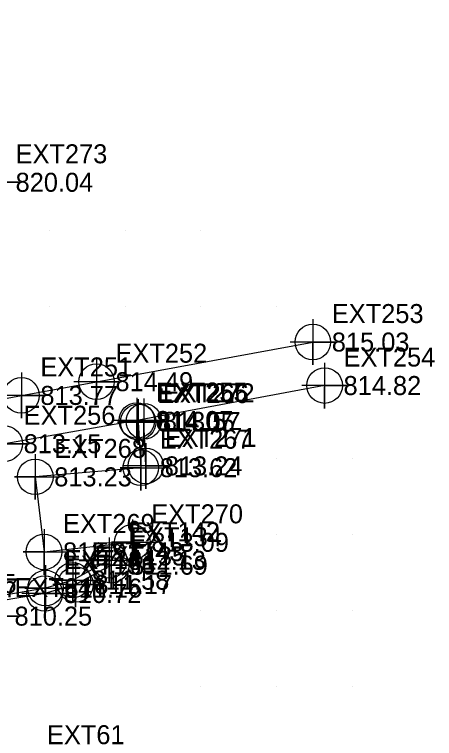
# Model space of a CAD drawing. Extents: x 1762120 to 1766775, y 709485 to 712965.
# Drawn here: x 1763875.4 to 1763930.8, y 712653.2 to 712748.4 of the extents above; entities that cross this region are included whole.
import ezdxf

# ---------------------------------------------------------------- set-up
doc = ezdxf.new("R2010")
doc.units = 0
for name, color, linetype in [('Exist Building Cogo Elevation', 7, 'Continuous'), ('Exist Building Cogo Number', 7, 'Continuous'), ('Exist Building Cogo Point CELL', 7, 'Continuous'), ('Exist DTM Drainline', 7, 'Continuous'), ('Exist DTM Drainline Cogo Elevation', 7, 'Continuous'), ('Exist DTM Drainline Cogo Number', 7, 'Continuous'), ('Exist DTM Drainline Cogo Point CELL', 7, 'Continuous'), ('Exist DTM QL2 LIDAR Elevation Point', 7, 'Continuous'), ('Exist Roads Curbs', 7, 'Continuous'), ('Exist Roads Curbs Cogo Elevation', 7, 'Continuous'), ('Exist Roads Curbs Cogo Number', 7, 'Continuous'), ('Exist Roads Curbs Cogo Point CELL', 7, 'Continuous'), ('Exist Roads EOP Cogo Elevation', 7, 'Continuous'), ('Exist Roads EOP Cogo Number', 7, 'Continuous'), ('Exist Roads EOP Cogo Point CELL', 7, 'Continuous'), ('Exist Roads EOP Other', 7, 'Continuous'), ('Exist Roads EOP Other Cogo Elevation', 7, 'Continuous'), ('Exist Roads EOP Other Cogo Number', 7, 'Continuous'), ('Exist Roads EOP Other Cogo Point CELL', 7, 'Continuous')]:
    doc.layers.add(name, color=color, linetype=linetype)

msp = doc.modelspace()

# ---------------------------------------------------------------- linework, layer by layer
at = {"layer": 'Exist Building Cogo Point CELL'}
msp.add_lwpolyline([(1763873.081, 712729.353), (1763873.081, 712723.353), (1763873.081, 712726.353), (1763876.081, 712726.353), (1763870.081, 712726.353)], dxfattribs=at)
at = {"layer": 'Exist DTM Drainline'}
msp.add_line((1763892.736, 712689.033), (1763892.48, 712694.893), dxfattribs=at)
msp.add_lwpolyline([(1763888.176, 712675.965), (1763883.465, 712673.426), (1763879.421, 712672.239), (1763861.295, 712669.219), (1763855.834, 712669.139), (1763849.992, 712671.404), (1763845.815, 712675.27), (1763843.641, 712680.197), (1763837.254, 712719.085), (1763830.877, 712756.626), (1763824.422, 712795.511), (1763818.53, 712833.611)], dxfattribs=at)
at = {"layer": 'Exist DTM Drainline Cogo Point CELL'}
for points in [[(1763892.48, 712697.893), (1763892.48, 712691.893), (1763892.48, 712694.893), (1763895.48, 712694.893), (1763889.48, 712694.893)], [(1763892.736, 712692.033), (1763892.736, 712686.033), (1763892.736, 712689.033), (1763895.736, 712689.033), (1763889.736, 712689.033)], [(1763888.176, 712678.965), (1763888.176, 712672.965), (1763888.176, 712675.965), (1763891.176, 712675.965), (1763885.176, 712675.965)], [(1763883.465, 712676.426), (1763883.465, 712670.426), (1763883.465, 712673.426), (1763886.465, 712673.426), (1763880.465, 712673.426)], [(1763879.421, 712675.239), (1763879.421, 712669.239), (1763879.421, 712672.239), (1763882.421, 712672.239), (1763876.421, 712672.239)]]:
    msp.add_lwpolyline(points, dxfattribs=at)
for centre in [(1763892.48, 712694.893), (1763892.736, 712689.033), (1763888.176, 712675.965), (1763883.465, 712673.426), (1763879.421, 712672.239)]:
    msp.add_circle(centre, 2.344, dxfattribs=at)
at = {"layer": 'Exist DTM QL2 LIDAR Elevation Point'}
for p, q in [((1763880, 712720), (1763880, 712720)), ((1763890, 712720), (1763890, 712720)), ((1763900, 712720), (1763900, 712720)), ((1763880, 712710), (1763880, 712710)), ((1763890, 712710), (1763890, 712710)), ((1763900, 712710), (1763900, 712710)), ((1763910, 712710), (1763910, 712710)), ((1763920, 712700), (1763920, 712700)), ((1763900, 712690), (1763900, 712690)), ((1763910, 712690), (1763910, 712690)), ((1763920, 712690), (1763920, 712690)), ((1763900, 712680), (1763900, 712680)), ((1763910, 712680), (1763910, 712680)), ((1763920, 712680), (1763920, 712680)), ((1763900, 712670), (1763900, 712670)), ((1763910, 712670), (1763910, 712670)), ((1763920, 712670), (1763920, 712670)), ((1763900, 712660), (1763900, 712660)), ((1763910, 712660), (1763910, 712660)), ((1763920, 712660), (1763920, 712660))]:
    msp.add_line(p, q, dxfattribs=at)
at = {"layer": 'Exist Roads Curbs'}
for points in [[(1763887.913, 712676.609), (1763883.105, 712673.993), (1763879.529, 712672.953), (1763861.13, 712669.797), (1763855.716, 712669.958), (1763851.546, 712671.351), (1763848.135, 712673.751), (1763845.524, 712677.19), (1763844.339, 712680.601), (1763837.881, 712719.135), (1763831.693, 712756.599), (1763825.169, 712795.603), (1763818.676, 712837.176), (1763818.589, 712840.745), (1763820.694, 712846.562), (1763822.71, 712849.767), (1763826.551, 712853.145), (1763830.571, 712855.107), (1763844.339, 712857.64), (1763850.134, 712857.271), (1763855.594, 712854.564), (1763859.316, 712849.842), (1763861.632, 712843.383)], [(1763891.733, 712694.8), (1763892.071, 712688.797), (1763878.17, 712687.59), (1763879.326, 712677.712), (1763890.96, 712678.974)]]:
    msp.add_lwpolyline(points, dxfattribs=at)
at = {"layer": 'Exist Roads Curbs Cogo Point CELL'}
for points in [[(1763891.733, 712697.8), (1763891.733, 712691.8), (1763891.733, 712694.8), (1763889.003, 712694.8), (1763894.733, 712694.8)], [(1763892.071, 712691.797), (1763892.071, 712685.797), (1763892.071, 712688.797), (1763889.341, 712688.797), (1763895.071, 712688.797)], [(1763878.17, 712690.59), (1763878.17, 712684.59), (1763878.17, 712687.59), (1763875.44, 712687.59), (1763881.17, 712687.59)], [(1763890.96, 712681.974), (1763890.96, 712675.974), (1763890.96, 712678.974), (1763888.23, 712678.974), (1763893.96, 712678.974)], [(1763879.326, 712680.712), (1763879.326, 712674.712), (1763879.326, 712677.712), (1763876.596, 712677.712), (1763882.326, 712677.712)], [(1763887.913, 712679.609), (1763887.913, 712673.609), (1763887.913, 712676.609), (1763885.183, 712676.609), (1763890.913, 712676.609)], [(1763883.105, 712676.993), (1763883.105, 712670.993), (1763883.105, 712673.993), (1763880.375, 712673.993), (1763886.105, 712673.993)], [(1763879.529, 712675.953), (1763879.529, 712669.953), (1763879.529, 712672.953), (1763876.799, 712672.953), (1763882.529, 712672.953)]]:
    msp.add_lwpolyline(points, dxfattribs=at)
for centre in [(1763891.733, 712694.8), (1763892.071, 712688.797), (1763878.17, 712687.59), (1763890.96, 712678.974), (1763879.326, 712677.712), (1763887.913, 712676.609), (1763883.105, 712673.993), (1763879.529, 712672.953)]:
    msp.add_circle(centre, 2.344, dxfattribs=at)
at = {"layer": 'Exist Roads EOP Cogo Point CELL'}
msp.add_lwpolyline([(1763872.939, 712672.264), (1763872.939, 712666.264), (1763872.939, 712669.264), (1763875.939, 712669.264), (1763869.939, 712669.264)], dxfattribs=at)
at = {"layer": 'Exist Roads EOP Other'}
for points in [[(1763851.484, 712693.757), (1763858.758, 712695.065), (1763876.347, 712698.307), (1763886.241, 712700.113), (1763914.739, 712705.328)], [(1763916.286, 712699.606), (1763891.551, 712695.001), (1763874.144, 712691.949), (1763852.567, 712687.92)]]:
    msp.add_lwpolyline(points, dxfattribs=at)
at = {"layer": 'Exist Roads EOP Other Cogo Point CELL'}
for points in [[(1763914.739, 712708.328), (1763914.739, 712702.328), (1763914.739, 712705.328), (1763917.739, 712705.328), (1763911.739, 712705.328)], [(1763886.241, 712703.113), (1763886.241, 712697.113), (1763886.241, 712700.113), (1763889.241, 712700.113), (1763883.241, 712700.113)], [(1763916.286, 712702.606), (1763916.286, 712696.606), (1763916.286, 712699.606), (1763919.286, 712699.606), (1763913.286, 712699.606)], [(1763876.347, 712701.307), (1763876.347, 712695.307), (1763876.347, 712698.307), (1763879.347, 712698.307), (1763873.347, 712698.307)], [(1763891.551, 712698.001), (1763891.551, 712692.001), (1763891.551, 712695.001), (1763894.551, 712695.001), (1763888.551, 712695.001)], [(1763874.144, 712694.949), (1763874.144, 712688.949), (1763874.144, 712691.949), (1763877.144, 712691.949), (1763871.144, 712691.949)]]:
    msp.add_lwpolyline(points, dxfattribs=at)
for centre in [(1763914.739, 712705.328), (1763886.241, 712700.113), (1763916.286, 712699.606), (1763876.347, 712698.307), (1763891.551, 712695.001), (1763874.144, 712691.949)]:
    msp.add_circle(centre, 2.344, dxfattribs=at)

# ---------------------------------------------------------------- texts
at = {"layer": 'Exist Building Cogo Elevation'}
msp.add_text('820.04', height=2.5, dxfattribs=at).set_placement((1763875.581, 712725.103))
at = {"layer": 'Exist Building Cogo Number'}
msp.add_text('EXT273', height=2.5, dxfattribs=at).set_placement((1763875.581, 712728.853))
at = {"layer": 'Exist DTM Drainline Cogo Elevation'}
for s, p in [('813.57', (1763894.98, 712693.643)), ('813.24', (1763895.236, 712687.783)), ('811.69', (1763890.676, 712674.715)), ('811.17', (1763885.965, 712672.176)), ('810.72', (1763881.921, 712670.989))]:
    msp.add_text(s, height=2.5, dxfattribs=at).set_placement(p)
at = {"layer": 'Exist DTM Drainline Cogo Number'}
for s, p in [('EXT272', (1763894.98, 712697.393)), ('EXT271', (1763895.236, 712691.533)), ('EXT134', (1763890.676, 712678.465)), ('EXT135', (1763885.965, 712675.926)), ('EXT136', (1763881.921, 712674.739)), ('EXT137', (1763863.795, 712671.719))]:
    msp.add_text(s, height=2.5, dxfattribs=at).set_placement(p)
at = {"layer": 'Exist Roads Curbs Cogo Elevation'}
for s, p in [('814.05', (1763894.233, 712693.55)), ('813.62', (1763894.571, 712687.547)), ('813.23', (1763880.67, 712686.34)), ('813.09', (1763893.46, 712677.724)), ('812.91', (1763881.826, 712676.462)), ('812.13', (1763890.413, 712675.359)), ('811.58', (1763885.605, 712672.743)), ('811.16', (1763882.029, 712671.703))]:
    msp.add_text(s, height=2.5, dxfattribs=at).set_placement(p)
at = {"layer": 'Exist Roads Curbs Cogo Number'}
for s, p in [('EXT266', (1763894.233, 712697.3)), ('EXT267', (1763894.571, 712691.297)), ('EXT268', (1763880.67, 712690.09)), ('EXT270', (1763893.46, 712681.474)), ('EXT269', (1763881.826, 712680.212)), ('EXT142', (1763890.413, 712679.109)), ('EXT143', (1763885.605, 712676.493)), ('EXT144', (1763882.029, 712675.453)), ('EXT145', (1763863.63, 712672.297))]:
    msp.add_text(s, height=2.5, dxfattribs=at).set_placement(p)
at = {"layer": 'Exist Roads EOP Cogo Elevation'}
msp.add_text('810.25', height=2.5, dxfattribs=at).set_placement((1763875.439, 712668.014))
at = {"layer": 'Exist Roads EOP Cogo Number'}
for s, p in [('EXT64', (1763875.439, 712671.764)), ('EXT61', (1763879.717, 712652.413))]:
    msp.add_text(s, height=2.5, dxfattribs=at).set_placement(p)
at = {"layer": 'Exist Roads EOP Other Cogo Elevation'}
for s, p in [('815.03', (1763917.239, 712704.078)), ('814.49', (1763888.741, 712698.863)), ('814.82', (1763918.786, 712698.356)), ('813.77', (1763878.847, 712697.057)), ('814.07', (1763894.051, 712693.751)), ('813.15', (1763876.644, 712690.699))]:
    msp.add_text(s, height=2.5, dxfattribs=at).set_placement(p)
at = {"layer": 'Exist Roads EOP Other Cogo Number'}
for s, p in [('EXT253', (1763917.239, 712707.828)), ('EXT252', (1763888.741, 712702.613)), ('EXT254', (1763918.786, 712702.106)), ('EXT251', (1763878.847, 712700.807)), ('EXT255', (1763894.051, 712697.501)), ('EXT256', (1763876.644, 712694.449))]:
    msp.add_text(s, height=2.5, dxfattribs=at).set_placement(p)

doc.saveas('drawing.dxf')
